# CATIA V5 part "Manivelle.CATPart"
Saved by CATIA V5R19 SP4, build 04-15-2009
Part number: Manivelle
Bounding box of the stored display mesh (mm): x 202.125 to 232.125, y 1215 to 1405, z 997.54 to 1264.169
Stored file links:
  G:\EU_thinkMotion\CFAO_2010\MMS_groupe1\MMS_groupe1\OK\rragonneau\rragonneau\Manivelle.CATPart
  F:\Squelette\Deambulateur.CATProduct
  G:\EU_thinkMotion\CFAO_2010\MMS_groupe1\MMS_groupe1\OK\rragonneau\rragonneau\Montants.CATPart
  G:\EU_thinkMotion\CFAO_2010\MMS_groupe1\MMS_groupe1\OK\rragonneau\rragonneau\Baudrier.CATPart
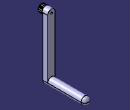
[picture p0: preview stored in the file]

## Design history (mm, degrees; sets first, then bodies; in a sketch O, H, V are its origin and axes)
External parameters (linked from other documents)
  `External.diam_moyeu_ext / epaisseur_bras&montant` = 60 mm
Set1
  Sketch1 on Plane1, origin (0, 1200, 0), H (-1, 0, 0), V (0, 0, 1)
    circle A1 centre (-217.1246, 1249.1687) radius 15
    radius A1 = 15 {= `External.diam_moyeu_ext / epaisseur_bras&montant` /4}
Set2
  Plane1: linked copy from another document
Body1 (main body)
  Pad1: profile Sketch1, direction (0, 1, 0), length 35 {= `External.diam_moyeu_ext / epaisseur_bras&montant` /4+20mm}, opposite side length -15 {= -`External.diam_moyeu_ext / epaisseur_bras&montant` /4}
  Sketch2 on end face of Pad1, origin (0, 1235, 0), H (-1, 0, 0), V (0, 0, 1)
    construction line L1 (-217.1246, 1249.1687) -> (-217.1246, 1012.5403)
    point P1 (-217.1246, 1249.1687)
    line L2 (-202.1246, 1249.1687) -> (-202.1246, 1012.5403)
    line L3 (-232.1246, 1012.5403) -> (-232.1246, 1249.1687)
    arc A1 centre (-217.1246, 1012.5403) radius 15 from (-202.1246, 1012.5403) to (-232.1246, 1012.5403) cw
    arc A2 centre (-217.1246, 1249.1687) radius 15 from (-232.1246, 1249.1687) to (-202.1246, 1249.1687) cw
    reference projected circle E1 centre (-217.1246, 1249.1687) radius 15 from edge [face of Pad1 from Sketch1.A1 | end face of Pad1]
    distance L1 L2 = 15 {= `External.diam_moyeu_ext / epaisseur_bras&montant` /4}
    vertical: L1 V
    tangency: A1 L2, A2 L2, A1 L3, A2 L3
    concentricity: P1 E1
  Pad2: profile Sketch2, direction (0, 1, 0), length 20
  Sketch3 on end face of Pad2, origin (215.1634, 1255, 1249.1687), H (1, 0, 0), V (0, 0, -1)
    point P1 (1.9612, 0)
    reference projected arc E1 centre (1.9612, 0) radius 15 from (-13.0388, 0) to (16.9612, 0) ccw from edge [face of Pad2 from Sketch2.A2 | end face of Pad2]
    concentricity: P1 E1
  Hole1: placed by Sketch3, at (217.1246, 1255, 1249.1687) direction (0, -1, 0), diameter 7.5 {= `External.diam_moyeu_ext / epaisseur_bras&montant` /8}, through (limit type 3)
  Sketch4 on end face of Pad2, origin (0, 1255, 0), H (-1, 0, 0), V (0, 0, 1)
    circle A1 centre (-217.1246, 1012.5403) radius 15
    reference projected arc E1 centre (-217.1246, 1012.5403) radius 15 from (-232.1246, 1012.5403) to (-202.1246, 1012.5403) ccw from edge [face of Pad2 from Sketch2.A1 | end face of Pad2]
    radius A1 = 15 {= `External.diam_moyeu_ext / epaisseur_bras&montant` /4}
    concentricity: E1 A1
  Pad3: profile Sketch4, direction (0, 1, 0), length 150
  Fillet1: radius 15 {= `External.diam_moyeu_ext / epaisseur_bras&montant` /4}, on end face of Pad3
  Sketch5 on start face of Pad1, origin (0, 1215, 0), H (1, 0, 0), V (0, 0, 1)
    line L1 (217.1246, 1259.1687) -> (214.6246, 1263.9589)
    point P1 (217.1246, 1259.1687)
    point P2 (214.6246, 1263.9589)
    axis line L2 (217.1246, 1255.2007) -> (217.1246, 1244.6581)
    point P5 (219.6246, 1263.9589)
    point P6 (217.1246, 1259.1687)
    line L3 (217.1246, 1259.1687) -> (219.6246, 1263.9589)
    reference projected circle E1 centre (217.1246, 1249.1687) radius 15 from edge [start face of Pad1 | face of Pad1 from Sketch1.A1]
    reference projected circle E2 centre (217.1246, 1249.1687) radius 15 from edge [start face of Pad1 | face of Pad1 from Sketch1.A1]
    reference projected circle E3 centre (217.1246, 1249.1687) radius 15 from edge [start face of Pad1 | face of Pad1 from Sketch1.A1]
    arc A1 centre (217.1246, 1261.7165) radius 3.3583 from (219.6246, 1263.9589) to (214.6246, 1263.9589) ccw
    distance L2 E1 = 15
    distance E2 P1 = 25 {= `External.diam_moyeu_ext / epaisseur_bras&montant` /2-5mm}
    distance P5 P2 = 5
    vertical: L2 V
    symmetry: P2 P5 L2, P1 P6 L2, L1 L3 L2
    coincidence: P1 L2, P2 E3, P1 P6
  Pocket1: profile Sketch5, direction (0, 1, 0), length 17
  CircPattern1: of Pocket1, instances 16, angular step 22.5 {= 360.0*1 deg/CircPattern1.AngularNumber}, axis from face of Hole1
